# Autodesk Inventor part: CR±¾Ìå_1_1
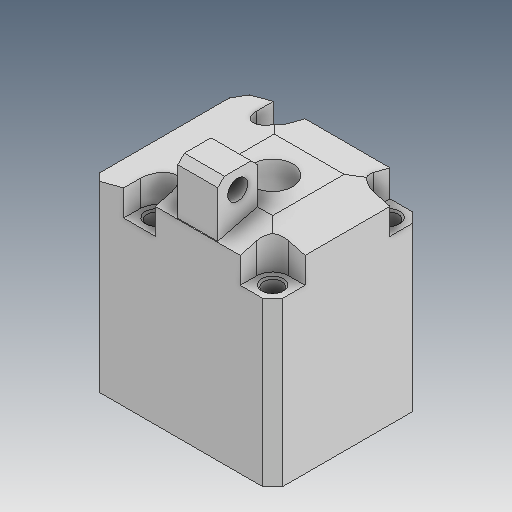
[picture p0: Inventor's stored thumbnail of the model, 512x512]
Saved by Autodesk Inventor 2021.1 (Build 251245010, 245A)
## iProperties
Created: 2019-04
Part Number: CR±¾Ìå_1_1
Material: Ogólny
Document SubType Name: Modeling
Designer: user
Density: 1 g/cm^3
Appearance: Domyślna
Author: user
Revision Number: ÈÎºÎ
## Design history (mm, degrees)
feature "ÊäÈë1"
feature "ÊäÈë2"
feature "ÊäÈë3"
node "Bryła1"
node "Bryła2"
node "Bryła3"
